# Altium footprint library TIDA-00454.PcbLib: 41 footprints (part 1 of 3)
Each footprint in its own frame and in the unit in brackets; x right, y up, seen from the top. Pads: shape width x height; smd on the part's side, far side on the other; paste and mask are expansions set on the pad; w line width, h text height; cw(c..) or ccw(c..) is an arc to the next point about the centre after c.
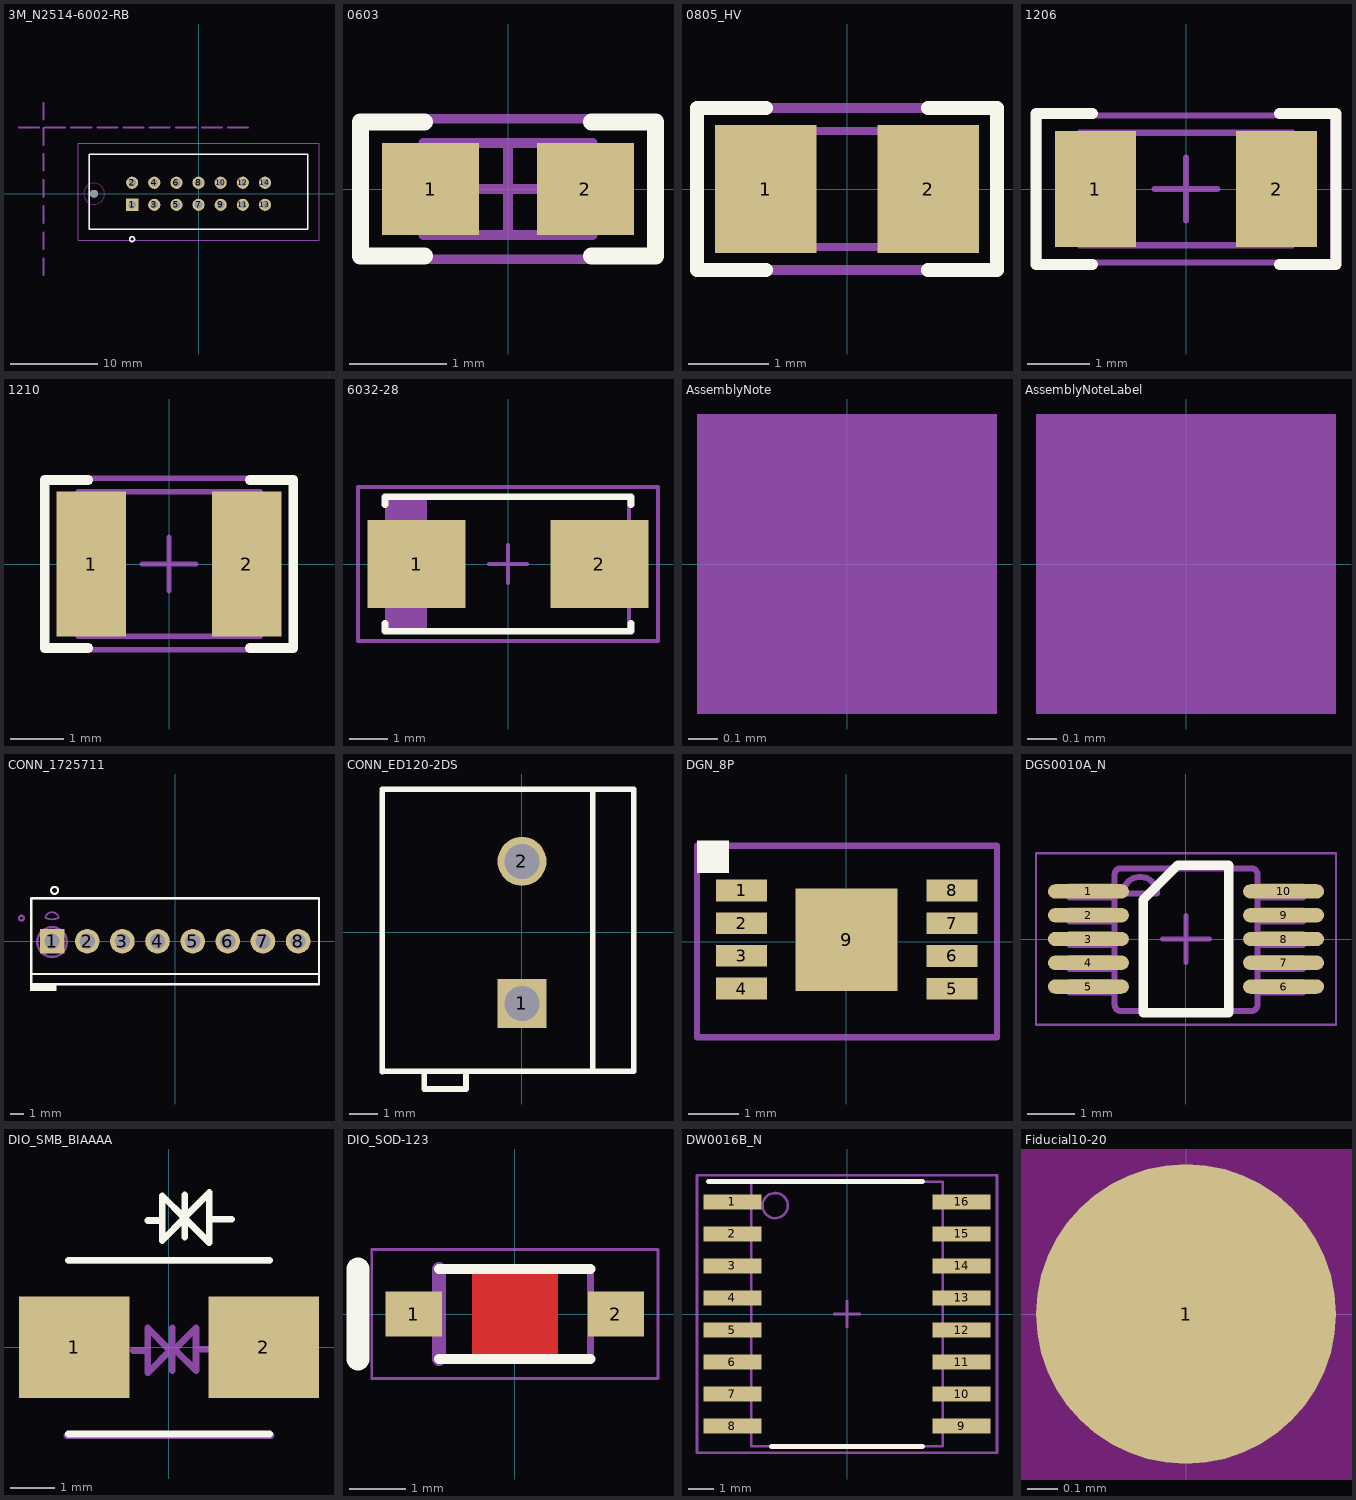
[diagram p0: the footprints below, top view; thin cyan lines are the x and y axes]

## 3M_N2514-6002-RB [mm] "CONN, HEADER, 14 POS, STRGHT GOLD"
height 9.91
pads (15):
  rect 1.4x1.4 / inner round 1.4 / far side rect 1.4x1.4 hole 0.889 mask+0.064: 1(-7.62,-1.27)
  round 1.4 hole 0.889 mask+0.064: 2(-7.62,1.27) 3(-5.08,-1.27) 4(-5.08,1.27) 5(-2.54,-1.27) 6(-2.54,1.27) 7(0,-1.27) 8(0,1.27) 9(2.54,-1.27) 10(2.54,1.27) 11(5.08,-1.27) 12(5.08,1.27) 13(7.62,-1.27) 14(7.62,1.27)
  round 0.889 hole 0.889 unplated mask+0.127: ""(-11.99,0)
Top Overlay:
  circle w0.178: c-7.62,-5.207 r0.279
  lines w0.178: -12.55,-4.07 12.55,-4.07 12.55,4.52 -12.55,4.52 -12.55,-4.07
Bottom Overlay:
  lines w0.178: -12.573,-4.07 -11.427,-4.07 ; -12.55,-4.07 -12.55,-3.023 ; -12.55,-2.413 -12.55,-1.499 ; -12.55,1.524 -12.55,2.438 ; -12.55,3 -12.55,4.52 -10.287,4.52 ; -10.713,-4.07 -8.427,-4.07 ; -9.573,4.52 -7.287,4.52 ; -9.446,4.52 -7.16,4.52 ; -7.713,-4.07 -5.427,-4.07 ; -6.446,4.52 -4.16,4.52 ; -4.713,-4.07 -2.427,-4.07 ; -3.446,4.52 -1.16,4.52 ; -1.713,-4.07 0.573,-4.07 ; -0.446,4.52 1.84,4.52 ; 1.287,-4.07 3.573,-4.07 ; 2.554,4.52 4.84,4.52 ; 4.287,-4.07 6.573,-4.07 ; 5.554,4.52 7.84,4.52 ; 7.287,-4.07 9.573,-4.07 ; 8.554,4.52 10.84,4.52 ; 10.287,-4.07 12.55,-4.07 12.55,-3.071 ; 11.43,4.52 12.55,4.52 12.55,3 ; 12.55,-1.953 12.55,-0.658 ; 12.55,0.46 12.55,1.755
Mechanical 5:
  circle w0.127: c-7.62,-5.207 r0.279
  lines w0.127: -12.55,-4.07 -12.55,4.52 12.55,4.52 12.55,-4.07 -12.55,-4.07
  text ".Designator" at -0.635,-1.016 h0.76
Mechanical 15:
  lines w0.05: -13.82,-5.34 -13.82,5.79 13.82,5.79 13.82,-5.34 -13.82,-5.34
Mechanical 16:
  lines w0.254: -20.605,7.62 -18.319,7.62 ; -17.78,-9.333 -17.78,-7.428 ; -17.78,-6.333 -17.78,-4.428 ; -17.78,-3.333 -17.78,-1.428 ; -17.78,-0.333 -17.78,1.572 ; -17.78,2.667 -17.78,4.572 ; -17.78,5.603 -17.78,7.508 ; -17.78,8.524 -17.78,10.429 ; -17.605,7.62 -15.319,7.62 ; -14.605,7.62 -12.319,7.62 ; -11.605,7.62 -9.319,7.62 ; -8.605,7.62 -6.319,7.62 ; -5.605,7.62 -3.319,7.62 ; -2.605,7.62 -0.319,7.62 ; 0.395,7.62 2.681,7.62 ; 3.395,7.62 5.681,7.62
Multi-Layer keep-out:
  circle w0.025: c-11.99,0 r1.206
Mechanical 17:
  text "DRILL TOLERANCE FOR NPTH HOLE IS +/-3 MIL" at -20.9,0.65 h1
  text "LEAD LENGTH: 2.84 MM" at -7.874,-3.429 h1
  text "RECOMMENDED BOARD THICKNESS: 62 MIL" at -16.637,2.413 h1
  text "MIN SIDE STACKABLE DISTANCE" at -47.498,7.239 h1
  text "MIN END STACKABLE DISTANCE" at -18.288,-11.049 h1
3D body: height 9.91, standoff 0, extent -12.55,-4.07 12.55,4.52

## 0603 [mm] "0603 from SM-752 data"
height 0.85
pads (2):
  rect 1x0.95 smd mask+0.064: 1(-0.8,0) 2(0.8,0)
Top Overlay:
  lines w0.178: -0.864,-0.691 -1.524,-0.691 -1.524,0.693 -0.864,0.693 ; 0.864,-0.691 1.524,-0.691 1.524,0.693 0.864,0.693
Mechanical 5:
  lines w0.1: -1.55,-0.725 1.55,-0.725 1.55,0.725 -1.55,0.725 -1.55,-0.725
  text ".Designator" at -0.986,-0.381 h0.76
Mechanical 13:
  lines w0.1: -0.55,-0.475 -0.55,0.475 ; 0.55,-0.475 0.55,0.475 ; -0.875,-0.475 -0.875,0.475 0.875,0.475 0.875,-0.475 -0.875,-0.475
Mechanical 15:
  lines w0.1: -0.475,0 0.475,0 ; 0,-0.475 0,0.475 ; -1.55,-0.725 -1.55,0.725 1.55,0.725 1.55,-0.725 -1.55,-0.725
3D body: height 0.85, standoff 0, extent 0.551,-0.474 0.874,0.474
3D body: height 0.85, standoff 0, extent -0.549,-0.474 0.549,0.474
3D body: height 0.85, standoff 0, extent -0.874,-0.474 -0.551,0.474

## 0805_HV [mil] "0805 with 30mil clearance between pads"
height 43.31
pads (2):
  rect 50x63 smd mask+2.5: 1(-40,0) 2(40,0)
Top Overlay:
  lines w7: -40,-40 -74,-40 -74,0 -74,40 -40,40 ; 40,-40 74,-40 74,0 74,40 40,40
Mechanical 5:
  lines w5: -74,-40 74,-40 74,40 -74,40 -74,-40
  text ".Designator" at -40,-13.8 h30
Mechanical 13:
  lines w3.94: -25.59,-28.54 -25.59,28.54 ; 25.59,-28.54 25.59,28.54 ; -43.31,-28.54 -43.31,28.54 43.31,28.54 43.31,-28.54 -43.31,-28.54
3D body: height 43.31, standoff 0, extent 25.61,-28.52 43.29,28.52
3D body: height 43.31, standoff 0, extent -25.57,-28.52 25.57,28.52
3D body: height 43.31, standoff 0, extent -43.29,-28.52 -25.61,28.52

## 1206 [mm] "1206 from SM-752 data"
height 1.35
pads (2):
  rect 1.3x1.85 smd mask+0.064: 1(-1.45,0) 2(1.45,0)
Top Overlay:
  lines w0.178: -1.5,-1.21 -2.4,-1.21 -2.4,1.21 -1.5,1.21 ; 1.5,-1.21 2.4,-1.21 2.4,1.21 1.5,1.21
Mechanical 5:
  lines w0.1: -1.7,-0.9 -1.7,0.9 1.7,0.9 1.7,-0.9 -1.7,-0.9
  text ".Designator" at -1.27,-0.381 h0.81
Mechanical 13:
  lines w0.1: -1.2,-0.9 -1.2,0.9 ; 1.2,-0.9 1.2,0.9 ; -1.7,-0.9 -1.7,0.9 1.7,0.9 1.7,-0.9 -1.7,-0.9
Mechanical 15:
  lines w0.1: -0.5,0 0.5,0 ; 0,-0.5 0,0.5 ; -2.35,-1.175 -2.35,1.175 2.35,1.175 2.35,-1.175 -2.35,-1.175
3D body: height 1.35, standoff 0, extent 1.201,-0.899 1.699,0.899
3D body: height 1.35, standoff 0, extent -1.199,-0.899 1.199,0.899
3D body: height 1.35, standoff 0, extent -1.699,-0.899 -1.201,0.899

## 1210 [mm] "1210 from SM-752 data"
height 1.35
pads (2):
  rect 1.3x2.7 smd mask+0.064: 1(-1.45,0) 2(1.45,0)
Top Overlay:
  lines w0.178: -1.511,-1.568 -2.316,-1.568 -2.316,1.568 -1.511,1.568 ; 1.511,-1.568 2.316,-1.568 2.316,1.568 1.511,1.568
Mechanical 5:
  lines w0.1: -1.7,-1.35 -1.7,1.35 1.7,1.35 1.7,-1.35 -1.7,-1.35
  text ".Designator" at 0.152,-0.965 h0.76
Mechanical 13:
  lines w0.1: -1.2,-1.35 -1.2,1.35 ; 1.2,-1.35 1.2,1.35 ; -1.7,-1.35 1.7,-1.35 1.7,1.35 -1.7,1.35 -1.7,-1.35
Mechanical 15:
  lines w0.1: -0.5,0 0.5,0 ; 0,-0.5 0,0.5 ; -2.35,-1.6 2.35,-1.6 2.35,1.6 -2.35,1.6 -2.35,-1.6
3D body: height 1.35, standoff 0, extent 1.201,-1.349 1.699,1.349
3D body: height 1.35, standoff 0, extent -1.199,-1.349 1.199,1.349
3D body: height 1.35, standoff 0, extent -1.699,-1.349 -1.201,1.349

## 6032-28 [mm] "Medium Density IPC based on Vishay Sprague 293D datasheet."
height 2.8
pads (2):
  rect 2.55x2.3 smd mask+0.064: 1(-2.375,0) 2(2.375,0)
Top Overlay:
  lines w0.178: -3.2,-1.539 -3.2,-1.75 3.2,-1.75 3.2,-1.539 ; -3.2,1.539 -3.2,1.75 3.2,1.75 3.2,1.539
Mechanical 5:
  rectangle: -3.15,-1.75 -2.15,1.75
  lines w0.1: -2.15,-1.75 -2.15,1.75 ; -3.15,-1.75 -3.15,1.75 3.15,1.75 3.15,-1.75 -3.15,-1.75
  text ".Designator" at 1.499,0.254 h0.76
Mechanical 15:
  lines w0.1: -0.5,0 0.5,0 ; 0,-0.5 0,0.5 ; -3.9,-2 3.9,-2 3.9,2 -3.9,2 -3.9,-2
3D body: height 2.8, standoff 0, extent -3.15,-1.75 3.15,1.75
3D body: height 2.8, standoff 2.8, extent -3.149,-1.749 -2.151,1.749

## AssemblyNote [mm] "Assembly Note"
Mechanical 5:
  rectangle: -0.508,-0.508 0.508,0.508
  text ".Comment" at 1.143,-0.508 h0.76
  text ".Designator" at -4.191,-0.508 h0.76

## AssemblyNoteLabel [mm] "Assembly Note for PCB Labels"
Mechanical 5:
  rectangle: -0.508,-0.508 0.508,0.508
  text "Install label in silkscreened box after final wash.  Text shall be 8 pt font.  Text shall be per the Label Table in the PDF schematic." at 1.143,-0.508 h0.76
  text ".Designator" at -4.191,-0.508 h0.76

## CONN_1725711 [mm] "Phoenix Contact"
height 13.8
pads (8):
  rect 1.78x1.78 hole 1.1 mask+0.064: 1(-8.89,0)
  round 1.78 hole 1.1 mask+0.064: 2(-6.35,0) 3(-3.81,0) 4(-1.27,0) 5(1.27,0) 6(3.81,0) 7(6.35,0) 8(8.89,0)
Top Overlay:
  circle w0.152: c-8.712,3.683 r0.254
  rectangle: -10.493,-3.6 -8.589,-3.1
  lines w0.178: -10.39,-2.361 10.39,-2.361 ; -10.404,-3.1 10.4,-3.1 10.4,3.1 -10.398,3.1 -10.404,-3.1
Mechanical 5:
  circle w0.152: c-11.102,1.676 r0.18
  lines w0.127: -10.39,-2.361 -10.39,-2.8 -10.39,-3.1 10.39,-3.1 10.39,-2.8 10.39,-2.361 ; -10.39,-2.361 -10.39,-1.51 -10.39,-1.22 -10.39,1.132 -10.39,1.417 -10.39,3.1 10.39,3.1 10.39,1.417 10.39,1.132 10.39,-1.22 10.39,-1.51 10.39,-2.361 ; -10.39,-2.361 10.39,-2.361 ; -9.788,-0.594 cw(c-8.89,-0.05) -8.89,1 cw(c-8.89,-0.05) -8.346,0.848 ; -9.788,-0.594 ccw(c-8.89,-0.05) -9.434,-0.948 ; -9.788,-0.594 -9.4,-0.206 -8.89,0.304 -8.684,0.51 -8.346,0.848 ; -9.434,-0.948 ccw(c-8.89,-0.05) -8.89,-1.1 ccw(c-8.89,-0.05) -7.992,0.494 ; -9.434,-0.948 -9.021,-0.534 -8.89,-0.403 -8.356,0.131 -7.992,0.494 ; -8.346,0.848 cw(c-8.89,-0.05) -7.992,0.494 ; -9.365,1.741 -9.363,1.733 -9.361,1.726 -9.357,1.719 -9.351,1.711 -9.345,1.704 -9.338,1.697 -9.329,1.691 -9.319,1.684 -9.309,1.677 -9.297,1.671 -9.284,1.665 -9.27,1.659 -9.255,1.653 -9.24,1.647 -9.223,1.642 -9.206,1.637 -9.188,1.632 -9.169,1.628 -9.149,1.624 -9.129,1.62 -9.108,1.616 -9.087,1.613 -9.065,1.61 -9.042,1.608 -9.02,1.606 -8.997,1.604 -8.973,1.602 -8.95,1.601 -8.926,1.6 -8.89,1.6 -8.866,1.6 -8.842,1.601 -8.819,1.602 -8.795,1.603 -8.772,1.605 -8.749,1.607 -8.727,1.609 -8.705,1.612 -8.683,1.615 -8.662,1.618 -8.641,1.622 -8.621,1.626 -8.602,1.63 -8.584,1.635 -8.566,1.639 -8.549,1.645 -8.533,1.65 -8.517,1.656 -8.503,1.662 -8.49,1.668 -8.477,1.674 -8.466,1.68 -8.456,1.687 -8.447,1.694 -8.439,1.701 -8.432,1.708 -8.426,1.715 -8.421,1.722 -8.418,1.729 -8.416,1.737 -8.415,1.744 -8.415,1.751 -8.417,1.763 ccw(c-8.89,1.6) -8.89,2.1 ccw(c-8.89,1.6) -9.363,1.763 -9.365,1.755 -9.365,1.748 -9.365,1.741 ; -8.89,-1.15 cw(c-8.89,-0.05) -8.89,1.05 cw(c-8.89,-0.05) -8.89,-1.15
  text ".Designator" at 0.559,1.778 h0.76
3D body: height 8.52, standoff -3.48, extent -10.39,-3.1 10.39,3.1

## CONN_ED120-2DS [mm] "ONSHORE"
height 13
pads (2):
  rect 1.75x1.75 hole 1.25 mask+0.064: 1(0,-2.54)
  round 1.75 hole 1.25 mask+0.064: 2(0,2.54)
Top Overlay:
  lines w0.2: -5,-4.985 -5,5.015 ; -5,-4.96 4,-4.96 ; -5,5.115 4,5.115 4,-4.885 ; -3.5,-4.96 -3.5,-5.6 -2,-5.6 -2,-4.96 ; 2.525,-4.95 2.525,5.05
Mechanical 5:
  lines w0.1: -5,-4.96 4,-4.96 ; -5,-4.885 -5,5.115 4,5.115 4,-4.885 ; -3.5,-4.96 -3.5,-5.6 -2,-5.6 -2,-4.96 ; 2.525,-4.875 2.525,5.125
  text ".Designator" at -1.524,-0.508 h0.76
3D body: height 13, standoff 0, extent -3.5,-5.6 -2,-4.925
3D body: height 5.7, standoff 4.3, extent -0.875,-3.204 4.125,-1.81
3D body: height 5.7, standoff 4.3, extent -0.85,1.846 4.15,3.24
3D body: height 13.1, standoff -2.5, extent -0.496,2.041 0.5,3.039
3D body: height 13.1, standoff -2.5, extent -0.496,-3.039 0.5,-2.041
3D body: height 13, standoff 0, extent -5,-4.985 4,5.115

## DGN_8P [mil]
pads (9):
  rect 40x17 smd mask+2.5: 1(-82.1,40) 2(-82.1,14.4) 3(-82.1,-11.2) 4(-82.1,-36.8) 5(82.9,-36.9) 6(82.9,-11.3) 7(82.9,14.3) 8(82.9,40)
  rect 80x80 smd mask+2.5: 9(0.2,1.4)
Top Overlay:
  region: -117,79 -92,79 -92,54 -117,54
Mechanical 5:
  lines w5: -117,-75 -117,75 118,75 118,-75 -117,-75
  text ".Designator" at -22,-16 h30
  text "*" at -105,30 h30

## DGS0010A_N [mm] "TSSOP, 10-Leads, Body 3x3mm, Pitch 0.5mm, IPC Medium Density"
height 1.1
pads (10):
  oval 1.7x0.3 smd mask+0.064: 1(-2.05,1) 2(-2.05,0.5) 3(-2.05,0) 4(-2.05,-0.5) 5(-2.05,-1) 6(2.05,-1) 7(2.05,-0.5) 8(2.05,0) 9(2.05,0.5) 10(2.05,1)
Top Overlay:
  lines w0.2: -0.9,-1.55 -0.9,0.825 -0.175,1.55 0.9,1.55 0.9,-1.55 -0.9,-1.55
Mechanical 5:
  lines w0.127: -2.45,-1.128 -2.21,-1.128 -2.09,-1.128 -2.087,-1.128 -1.784,-1.128 -1.498,-1.128 -1.498,-0.899 -1.784,-0.899 -2.087,-0.899 -2.09,-0.899 -2.21,-0.899 -2.45,-0.899 -2.45,-1.128 ; -2.45,-0.628 -2.21,-0.628 -2.09,-0.628 -2.087,-0.628 -1.784,-0.628 -1.498,-0.628 -1.498,-0.4 -1.784,-0.4 -2.087,-0.4 -2.09,-0.4 -2.21,-0.4 -2.45,-0.4 -2.45,-0.628 ; -2.45,-0.128 -2.21,-0.128 -2.09,-0.128 -2.087,-0.128 -1.784,-0.128 -1.498,-0.128 -1.498,0.1 -1.784,0.1 -2.087,0.1 -2.09,0.1 -2.21,0.1 -2.45,0.1 -2.45,-0.128 ; -2.45,0.372 -2.21,0.372 -2.09,0.372 -2.087,0.372 -1.784,0.372 -1.498,0.372 -1.498,0.6 -1.784,0.6 -2.087,0.6 -2.09,0.6 -2.21,0.6 -2.45,0.6 -2.45,0.372 ; -2.45,0.871 -2.21,0.871 -2.09,0.871 -2.087,0.871 -1.784,0.871 -1.498,0.871 -1.498,1.1 -1.784,1.1 -2.087,1.1 -2.09,1.1 -2.21,1.1 -2.45,1.1 -2.45,0.871 ; -1.497,-1.388 ccw(c-1.37,-1.386) -1.373,-1.513 -1.371,-1.513 1.373,-1.513 1.375,-1.513 ccw(c1.373,-1.386) 1.5,-1.388 1.5,-1.386 1.5,1.358 1.5,1.36 ccw(c1.373,1.358) 1.375,1.485 1.373,1.485 -1.371,1.485 -1.373,1.485 ccw(c-1.37,1.358) -1.497,1.36 -1.498,1.358 -1.498,-1.386 -1.497,-1.388 ; -1.32,0.951 cw(c-0.964,0.951) -0.609,0.951 -1.32,0.951 ; 1.5,-1.128 1.786,-1.128 2.089,-1.128 2.093,-1.128 2.213,-1.128 2.452,-1.128 2.452,-0.899 2.213,-0.899 2.093,-0.899 2.089,-0.899 1.786,-0.899 1.5,-0.899 1.5,-1.128 ; 1.5,-0.628 1.786,-0.628 2.089,-0.628 2.093,-0.628 2.213,-0.628 2.452,-0.628 2.452,-0.4 2.213,-0.4 2.093,-0.4 2.089,-0.4 1.786,-0.4 1.5,-0.4 1.5,-0.628 ; 1.5,-0.128 1.786,-0.128 2.089,-0.128 2.093,-0.128 2.213,-0.128 2.452,-0.128 2.452,0.1 2.213,0.1 2.093,0.1 2.089,0.1 1.786,0.1 1.5,0.1 1.5,-0.128 ; 1.5,0.372 1.786,0.372 2.089,0.372 2.093,0.372 2.213,0.372 2.452,0.372 2.452,0.6 2.213,0.6 2.093,0.6 2.089,0.6 1.786,0.6 1.5,0.6 1.5,0.372 ; 1.5,0.871 1.786,0.871 2.089,0.871 2.093,0.871 2.213,0.871 2.452,0.871 2.452,1.1 2.213,1.1 2.093,1.1 2.089,1.1 1.786,1.1 1.5,1.1 1.5,0.871
  text ".Designator" at 0.686,0.178 h0.76
Mechanical 15:
  lines w0.05: -3.15,-1.8 3.15,-1.8 3.15,1.8 -3.15,1.8 -3.15,-1.8
  lines w0.1: -0.5,0 0.5,0 ; 0,-0.5 0,0.5
3D body: height 0.94, standoff -0.02, extent -2.451,-1.499 2.451,1.498

## DIO_SMB_BIAAAA [mm]
height 2.28
pads (2):
  rect 2.5x2.3 smd mask+0.064: 1(-2.15,0) 2(2.15,0)
Top Overlay:
  lines w0.152: -2.285,-1.97 2.285,-1.97 ; -2.285,1.97 2.285,1.97 ; -0.483,2.87 -0.178,2.87 ; 0.356,2.489 0.356,3.454 ; 0.406,2.997 0.914,3.505 0.914,2.362 0.356,2.921 ; 1.016,2.896 1.422,2.896 ; 0.356,2.921 -0.152,2.413 -0.152,2.616 -0.152,3.429 0.356,2.921
Mechanical 5:
  lines w0.152: -2.311,-2.007 2.311,-2.007 ; -2.286,1.956 2.286,1.956 ; -0.813,-0.076 -0.508,-0.076 ; 0.076,-0.533 0.076,0.432 ; 0.686,-0.051 0.965,-0.051 ; 0.025,-0.076 -0.483,0.432 -0.483,-0.381 -0.483,-0.584 0.025,-0.076 ; 0.025,-0.076 0.102,-0.076 ; 0.025,-0.076 0.102,-0.076 ; 0.102,-0.076 0.61,0.432 0.61,-0.533 0.152,-0.076 ; 0.102,-0.076 0.152,-0.076 ; 0.102,-0.076 0.152,-0.076
  text ".designator" at 1.702,-0.457 h0.89
Mechanical 15:
  lines w0.025: -2.285,-1.97 2.285,-1.97 ; -2.285,1.97 2.285,1.97

## DIO_SOD-123 [mm] "DIODE, SCHOTTKY, SOD-123"
height 1.35
pads (2):
  rect 1x0.8 smd mask+0.064: 1(-1.8,0) 2(1.8,0)
Top Layer:
  region: -0.762,0.8 0.762,0.8 0.762,-0.8 -0.762,-0.8
Top Overlay:
  lines w0.178: -1.35,-0.8 1.35,-0.8 ; -1.35,0.8 1.35,0.8
  lines w0.406: -2.794,-0.8 -2.794,0.8
Mechanical 5:
  lines w0.127: -1.35,-0.8 1.35,-0.8 1.35,0.8 -1.35,0.8
  lines w0.254: -1.35,-0.8 -1.35,0.8
  text ".Designator" at 0.508,0.508 h0.76
Mechanical 15:
  lines w0.05: -2.55,-1.15 -2.55,1.15 2.55,1.15 2.55,-1.15 -2.55,-1.15
3D body: height 1.35, standoff 0, extent -1.35,-0.8 1.35,0.8

## DW0016B_N [mm] "SOP, 16-Leads, Body 10.5x7.6mm (max), Pitch 1.27mm, IPC Medium Density"
height 2.65
pads (16):
  rect 2.3x0.6 smd mask+0.064: 1(-4.55,4.445) 2(-4.55,3.175) 3(-4.55,1.905) 4(-4.55,0.635) 5(-4.55,-0.635) 6(-4.55,-1.905) 7(-4.55,-3.175) 8(-4.55,-4.445) 9(4.55,-4.445) 10(4.55,-3.175) 11(4.55,-1.905) 12(4.55,-0.635) 13(4.55,0.635) 14(4.55,1.905) 15(4.55,3.175) 16(4.55,4.445)
Top Overlay:
  lines w0.2: -5.5,5.25 3,5.25 ; -3,-5.25 3,-5.25
Mechanical 5:
  circle w0.1: c-2.85,4.3 r0.5
  lines w0.1: -3.8,-5.25 3.8,-5.25 3.8,5.25 -3.8,5.25 -3.8,-5.25
  text ".Designator" at -0.584,-0.102 h0.76
Mechanical 15:
  lines w0.1: -0.5,0 0.5,0 ; 0,-0.5 0,0.5 ; -5.95,-5.5 5.95,-5.5 5.95,5.5 -5.95,5.5 -5.95,-5.5
3D body: height 2.65, standoff 0.1, extent -3.8,-5.25 3.8,5.25
3D body: height 2.66, standoff 2.65, extent -3.247,3.851 -2.45,4.649

## Fiducial10-20 [mm]
pads (1):
  round 1 smd paste+0 mask+0.5: 1(0,0)
Top Layer keep-out:
  circle w1.178: c0,0 r0.5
